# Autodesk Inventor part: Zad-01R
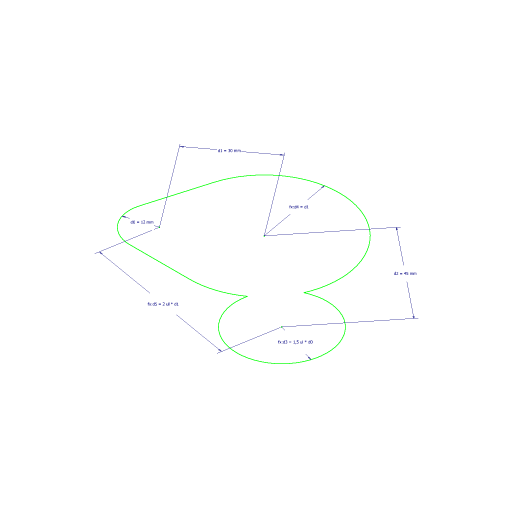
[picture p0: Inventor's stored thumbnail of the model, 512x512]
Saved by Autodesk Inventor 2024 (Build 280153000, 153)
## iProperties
Company: ATC
Shininess: 20.0
Length Units: 11269
Angle Units: 11279
Time Units: 11290
Mass Units: 11283
Angle Display Precision: 2
Created: 2023-03
Part Number: Zad-01R
Document SubType Name: Modeling
Designer: Andrzej Jaskulski
Density: 1 g/cm^3
Material: Kurs-AJ
Appearance: Kurs-AJ
Checked By: A.J.
Engr Approved By: Andrzej Jaskulski
Mfg Approved By: Andrzej Jaskulski
Authority: A.J.
Density: 0.0
Volumn: 0.0
Area: 0.0
PropertySet Name: Model Information
Control State: 0
Master: False
Checked Out: False
Title: A.J.: Kurs R2024-MEP
Author: Andrzej Jaskulski
Revision Number: 1/24
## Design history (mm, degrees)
sketch "Zad 01R"
  geometry: L1 (-11.52, 3.36)-(-4.8, 26.4); L2 (0, -12)-(24, -12); A1 r 18 centre (59.143, -10.107) between (41.542, -6.337) and (51.597, 6.235); A2 r 12 centre (0, 0) between (-11.52, 3.36) and (0, -12); A3 r 30 centre (24, 18) between (24, -12) and (41.542, -6.337); A4 r 30 centre (24, 18) between (51.597, 6.235) and (-4.8, 26.4)
  constraints: 8 point on circle, 4 centre point, 4 end point, 4 tangent, 1 horizontal
  dimensions: "d0" = 12 radius of A2; "d1" = 30 distance of A3.centre A2.centre; "d2" = 45 distance of A1.centre A3.centre; "d3" = 18 radius of A1 (= 1.5 x d0); "d4" = 30 radius of A4 (= d1); "d5" = 60 distance of A1.centre A2.centre (= 2 x d1)
node "Korpusy bryłowe"
node "Korpusy powierzchniowe"
